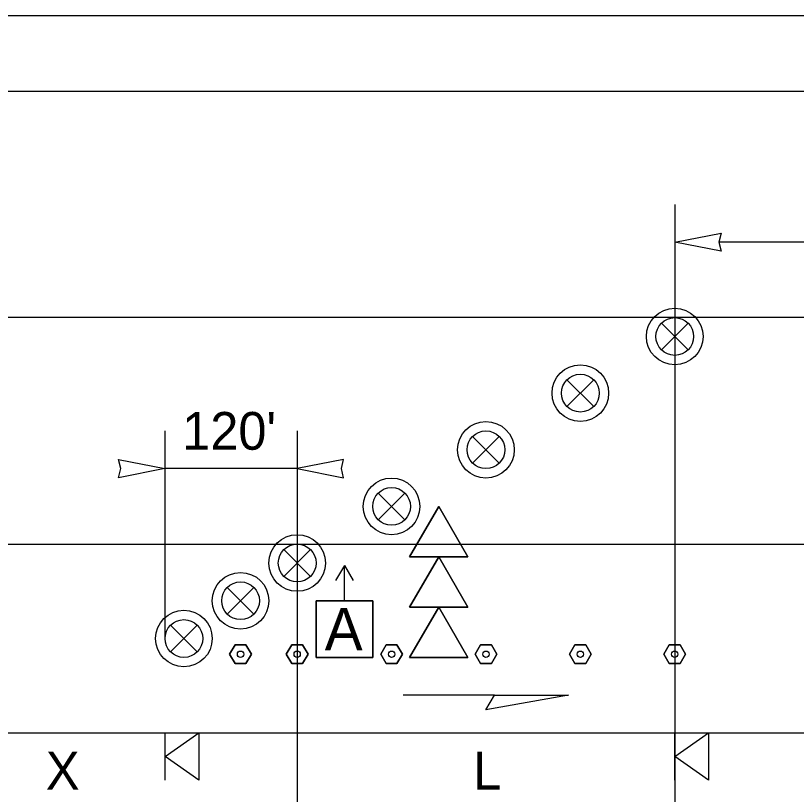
# Model space of a CAD drawing. Extents: x 99958 to 100136, y 99935 to 100013.
# Drawn here: x 100025.894 to 100027.548, y 99945.105 to 99946.756 of the extents above; entities that cross this region are included whole.
import ezdxf

# ---------------------------------------------------------------- set-up
doc = ezdxf.new("R2010")
doc.units = 0
for name, color, linetype in [('RD_ED_ShoulderPavedEdge', 7, 'Continuous'), ('RD_MK_LineEdgeWhite', 7, 'Continuous'), ('RD_MK_LineEdgeYellow', 7, 'Continuous'), ('RD_MK_LineLane', 7, 'Continuous'), ('TR_WZ_PortableSignMountBlk-Wht', 7, 'Continuous'), ('TR_WZ_SequentialArrowSign', 7, 'Continuous'), ('TR_WZ_TrafficSafetyDrum', 7, 'Continuous'), ('TR_WZ_TubularMarker', 7, 'Continuous'), ('TR_WZ_WorkZoneDetails', 7, 'Continuous'), ('TR_WZ_WorkZoneTextCurrent', 7, 'Continuous')]:
    doc.layers.add(name, color=color, linetype=linetype)

msp = doc.modelspace()

# ---------------------------------------------------------------- linework, layer by layer
at = {"layer": 'RD_ED_ShoulderPavedEdge'}
for p, q in [((100021.7753, 99946.7557), (100035.62, 99946.7557)), ((100021.7753, 99945.2357), (100035.62, 99945.2357))]:
    msp.add_line(p, q, dxfattribs=at)
at = {"layer": 'RD_MK_LineEdgeWhite'}
msp.add_line((100021.7753, 99945.6357), (100035.62, 99945.6357), dxfattribs=at)
at = {"layer": 'RD_MK_LineEdgeYellow'}
msp.add_line((100021.7753, 99946.5957), (100035.62, 99946.5957), dxfattribs=at)
at = {"layer": 'RD_MK_LineLane'}
msp.add_lwpolyline([(100035.62, 99946.1157), (100021.7753, 99946.1157)], dxfattribs=at)
at = {"layer": 'TR_WZ_PortableSignMountBlk-Wht'}
for p, q in [((100026.2103, 99945.1357), (100026.2103, 99945.2357)), ((100027.2902, 99945.1357), (100027.2902, 99945.2357))]:
    msp.add_line(p, q, dxfattribs=at)
for points in [[(100026.2103, 99945.1856), (100026.2821, 99945.2357), (100026.2821, 99945.1357)], [(100027.2902, 99945.1856), (100027.3621, 99945.2357), (100027.3621, 99945.1357)]]:
    msp.add_lwpolyline(points, close=True, dxfattribs=at)
at = {"layer": 'TR_WZ_SequentialArrowSign'}
for points in [[(100026.7903, 99945.7157), (100026.7285, 99945.6091), (100026.7903, 99945.6091), (100026.852, 99945.6091), (100026.7903, 99945.7157)], [(100026.852, 99945.6091), (100026.7903, 99945.6091), (100026.7285, 99945.6091), (100026.7903, 99945.7157), (100026.852, 99945.6091)], [(100026.7903, 99945.6091), (100026.7285, 99945.5024), (100026.7903, 99945.5024), (100026.852, 99945.5024), (100026.7903, 99945.6091)], [(100026.852, 99945.5024), (100026.7903, 99945.5024), (100026.7285, 99945.5024), (100026.7903, 99945.6091), (100026.852, 99945.5024)], [(100026.7903, 99945.5024), (100026.7285, 99945.3957), (100026.852, 99945.3957), (100026.7903, 99945.5024)], [(100026.852, 99945.3957), (100026.7285, 99945.3957), (100026.7903, 99945.5024), (100026.852, 99945.3957)]]:
    msp.add_lwpolyline(points, dxfattribs=at)
at = {"layer": 'TR_WZ_TrafficSafetyDrum'}
for p, q in [((100027.262, 99946.104), (100027.3186, 99946.0474)), ((100027.3186, 99946.104), (100027.262, 99946.0474)), ((100027.062, 99945.984), (100027.1186, 99945.9274)), ((100027.1186, 99945.984), (100027.062, 99945.9274)), ((100026.862, 99945.864), (100026.9186, 99945.8074)), ((100026.9186, 99945.864), (100026.862, 99945.8074)), ((100026.662, 99945.744), (100026.7186, 99945.6874)), ((100026.7186, 99945.744), (100026.662, 99945.6874)), ((100026.462, 99945.624), (100026.5186, 99945.5674)), ((100026.5186, 99945.624), (100026.462, 99945.5674)), ((100026.342, 99945.544), (100026.3986, 99945.4874)), ((100026.3986, 99945.544), (100026.342, 99945.4874)), ((100026.222, 99945.464), (100026.2786, 99945.4074)), ((100026.2786, 99945.464), (100026.222, 99945.4074))]:
    msp.add_line(p, q, dxfattribs=at)
for centre, radius in [((100027.2903, 99946.0757), 0.06), ((100027.2903, 99946.0757), 0.06), ((100027.2903, 99946.0757), 0.04), ((100027.0903, 99945.9557), 0.06), ((100027.0903, 99945.9557), 0.06), ((100027.0903, 99945.9557), 0.04), ((100026.8903, 99945.8357), 0.06), ((100026.8903, 99945.8357), 0.06), ((100026.8903, 99945.8357), 0.04), ((100026.6903, 99945.7157), 0.06), ((100026.6903, 99945.7157), 0.06), ((100026.6903, 99945.7157), 0.04), ((100026.4903, 99945.5957), 0.06), ((100026.4903, 99945.5957), 0.06), ((100026.4903, 99945.5957), 0.04), ((100026.3703, 99945.5157), 0.06), ((100026.3703, 99945.5157), 0.06), ((100026.3703, 99945.5157), 0.04), ((100026.2503, 99945.4357), 0.06), ((100026.2503, 99945.4357), 0.06), ((100026.2503, 99945.4357), 0.04)]:
    msp.add_circle(centre, radius, dxfattribs=at)
at = {"layer": 'TR_WZ_TubularMarker'}
for points in [[(100026.3472, 99945.4024), (100026.3587, 99945.4224), (100026.3818, 99945.4224), (100026.3934, 99945.4024), (100026.3818, 99945.3824), (100026.3587, 99945.3824)], [(100026.4672, 99945.4024), (100026.4787, 99945.4224), (100026.5018, 99945.4224), (100026.5134, 99945.4024), (100026.5018, 99945.3824), (100026.4787, 99945.3824)], [(100026.6672, 99945.4024), (100026.6787, 99945.4224), (100026.7018, 99945.4224), (100026.7134, 99945.4024), (100026.7018, 99945.3824), (100026.6787, 99945.3824)], [(100026.8672, 99945.4024), (100026.8787, 99945.4224), (100026.9018, 99945.4224), (100026.9134, 99945.4024), (100026.9018, 99945.3824), (100026.8787, 99945.3824)], [(100027.0672, 99945.4024), (100027.0787, 99945.4224), (100027.1018, 99945.4224), (100027.1134, 99945.4024), (100027.1018, 99945.3824), (100027.0787, 99945.3824)], [(100027.2672, 99945.4024), (100027.2787, 99945.4224), (100027.3018, 99945.4224), (100027.3134, 99945.4024), (100027.3018, 99945.3824), (100027.2787, 99945.3824)]]:
    msp.add_lwpolyline(points, close=True, dxfattribs=at)
for points in [[(100026.3587, 99945.3824), (100026.3818, 99945.3824), (100026.3934, 99945.4024), (100026.3818, 99945.4224), (100026.3587, 99945.4224), (100026.3472, 99945.4024), (100026.3587, 99945.3824)], [(100026.4787, 99945.3824), (100026.5018, 99945.3824), (100026.5134, 99945.4024), (100026.5018, 99945.4224), (100026.4787, 99945.4224), (100026.4672, 99945.4024), (100026.4787, 99945.3824)], [(100026.6787, 99945.3824), (100026.7018, 99945.3824), (100026.7134, 99945.4024), (100026.7018, 99945.4224), (100026.6787, 99945.4224), (100026.6672, 99945.4024), (100026.6787, 99945.3824)], [(100026.8787, 99945.3824), (100026.9018, 99945.3824), (100026.9134, 99945.4024), (100026.9018, 99945.4224), (100026.8787, 99945.4224), (100026.8672, 99945.4024), (100026.8787, 99945.3824)], [(100027.0787, 99945.3824), (100027.1018, 99945.3824), (100027.1134, 99945.4024), (100027.1018, 99945.4224), (100027.0787, 99945.4224), (100027.0672, 99945.4024), (100027.0787, 99945.3824)], [(100027.2787, 99945.3824), (100027.3018, 99945.3824), (100027.3134, 99945.4024), (100027.3018, 99945.4224), (100027.2787, 99945.4224), (100027.2672, 99945.4024), (100027.2787, 99945.3824)]]:
    msp.add_lwpolyline(points, dxfattribs=at)
for centre in [(100026.3703, 99945.4024), (100026.4903, 99945.4024), (100026.6903, 99945.4024), (100026.8903, 99945.4024), (100027.0903, 99945.4024), (100027.2903, 99945.4024)]:
    msp.add_circle(centre, 0.00667, dxfattribs=at)
at = {"layer": 'TR_WZ_WorkZoneDetails'}
for p, q in [((100027.2902, 99946.3557), (100027.2902, 99944.598)), ((100030.1965, 99946.2757), (100027.384, 99946.2757)), ((100026.2102, 99945.8757), (100026.2102, 99945.4357)), ((100026.4902, 99945.8757), (100026.4902, 99944.9957)), ((100026.4902, 99945.7957), (100026.2102, 99945.7957)), ((100026.5903, 99945.5907), (100026.5715, 99945.5583)), ((100026.5903, 99945.5157), (100026.5903, 99945.5907)), ((100026.5903, 99945.5907), (100026.609, 99945.5583)), ((100026.9081, 99945.3157), (100026.7152, 99945.3157))]:
    msp.add_line(p, q, dxfattribs=at)
for points in [[(100027.2902, 99946.2757), (100027.3885, 99946.295), (100027.384, 99946.2757), (100027.3885, 99946.2565)], [(100026.2102, 99945.7957), (100026.112, 99945.7765), (100026.1165, 99945.7957), (100026.112, 99945.815)], [(100026.4902, 99945.7957), (100026.5885, 99945.7765), (100026.584, 99945.7957), (100026.5885, 99945.815)], [(100026.5303, 99945.5157), (100026.6503, 99945.5157), (100026.6503, 99945.3957), (100026.5303, 99945.3957)], [(100027.0653, 99945.3157), (100026.8902, 99945.2849), (100026.9081, 99945.3157)]]:
    msp.add_lwpolyline(points, close=True, dxfattribs=at)
msp.add_lwpolyline([(100026.5303, 99945.5157), (100026.5303, 99945.3957), (100026.6503, 99945.3957), (100026.6503, 99945.5157), (100026.5903, 99945.5157), (100026.5303, 99945.5157)], dxfattribs=at)

# ---------------------------------------------------------------- texts
msp.add_text('A', height=0.09, dxfattribs=at).set_placement((100026.5487, 99945.4107))
at = {"layer": 'TR_WZ_WorkZoneTextCurrent'}
msp.add_text("120'", height=0.08, dxfattribs=at).set_placement((100026.2467, 99945.8357))
for s, p in [('X', (100025.9578, 99945.1157)), ('L', (100026.8631, 99945.1157))]:
    msp.add_text(s, height=0.08, rotation=360, dxfattribs=at).set_placement(p)

doc.saveas('drawing.dxf')
